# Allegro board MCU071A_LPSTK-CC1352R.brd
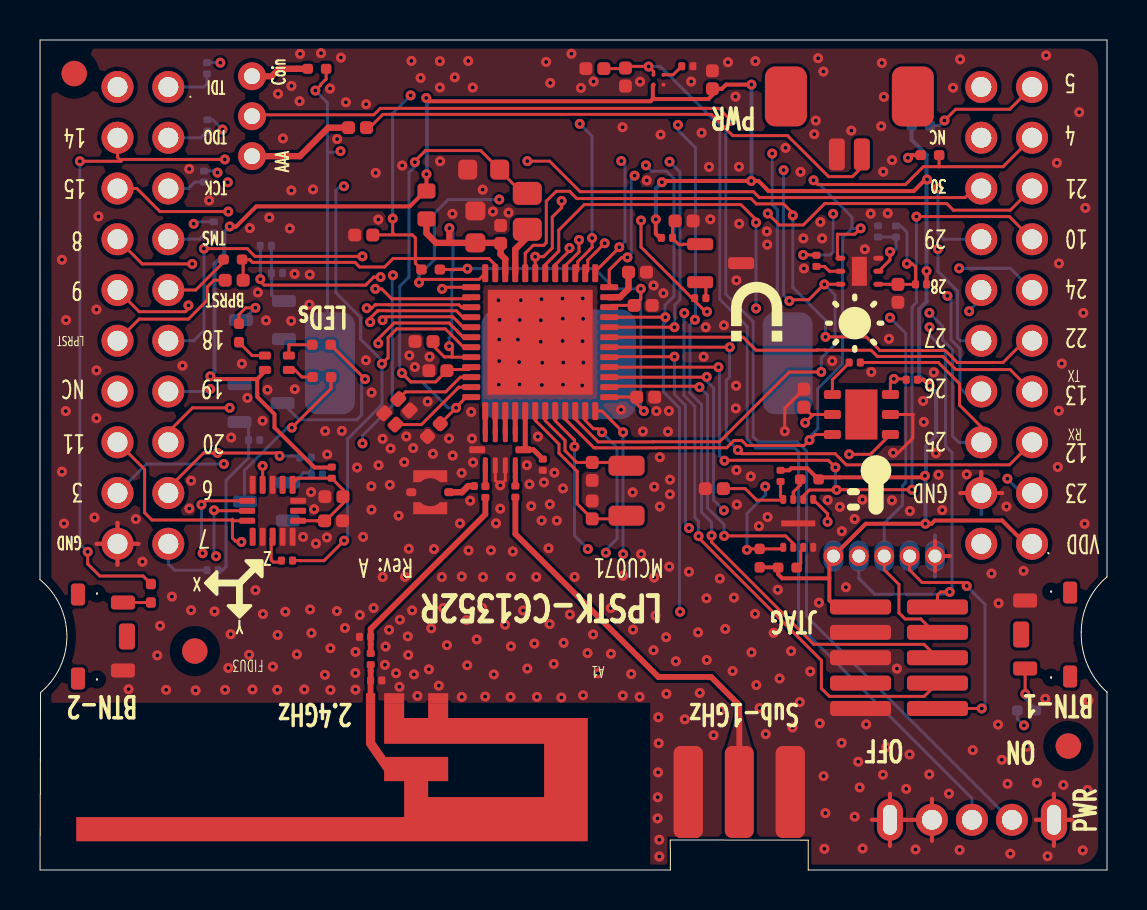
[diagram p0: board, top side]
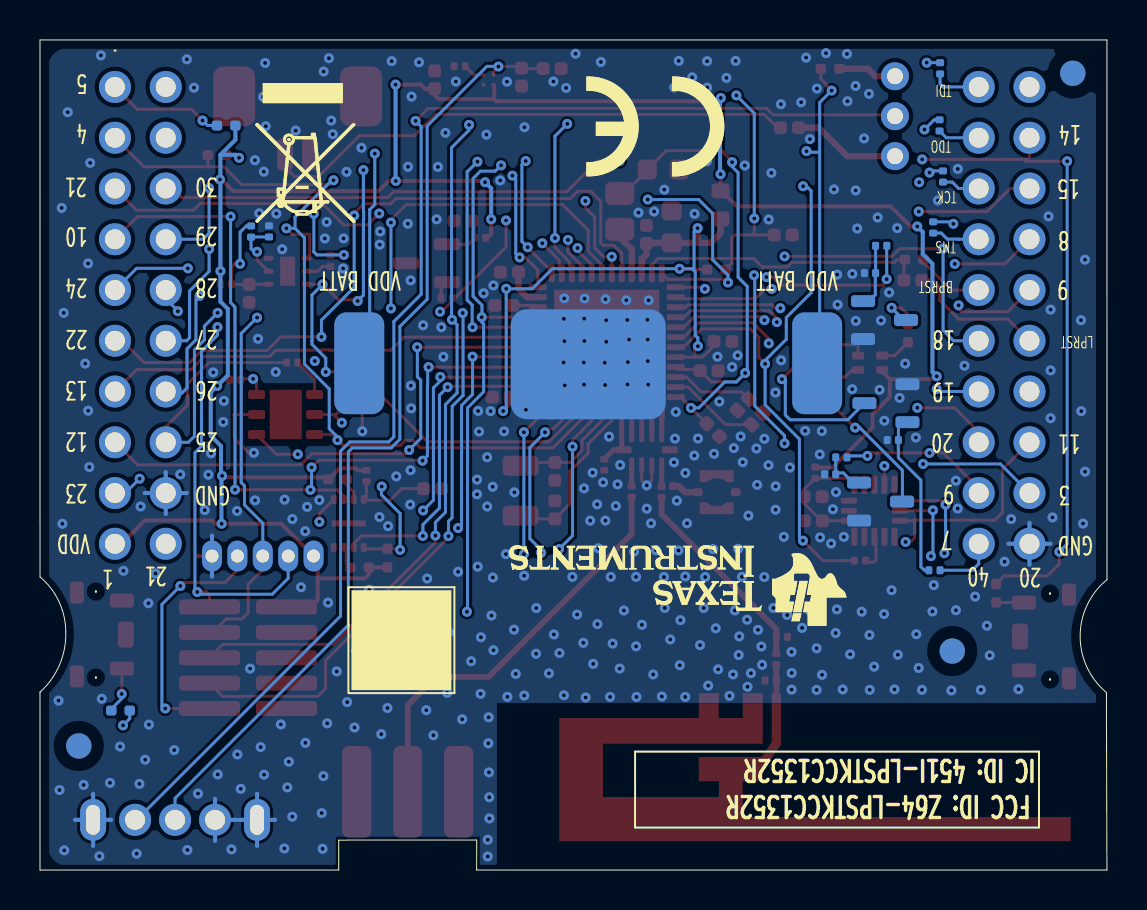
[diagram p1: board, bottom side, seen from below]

Outline 53.37 x 41.54 mm; copper layers: TOP, L2, L3, BOTTOM. Coordinates in mm from the lower left corner of the outline.
Outline path: 0,14.53 arc(1.35,11.71) 0.03,8.88 arc(0.03,8.84) 0.03,8.81 0,0 31.53,0 31.52,1.5 38.43,1.5 38.42,0 53.37,0 53.37,8.91 53.36,8.9 arc(52.39,10.27) 52.08,11.91 arc(52.42,13.43) 53.36,14.67 53.37,41.54 0,41.54 0,14.53

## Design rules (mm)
constraint set DEFAULT: min track width 0.15

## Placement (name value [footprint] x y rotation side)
A1  2.4GHz  [ANTENNA_DN007N]  16.53 8.6 180 top
BT1  BAT-HLD-001  [BAT_BATHLD001N]  37.4 25.36 180 bottom
C1  22uF  [CAPC1608X100A2N]  22.99 35.05 180 top
C2  100nF  [CAPC1005X60A2N]  20.35 24.99 180 top
C3  100nF  [CAPC1005X60A2N]  20.02 22.34 225 top
C4  100nF  [CAPC1005X60A2N]  29.84 23.67 0 top
C5  100nF  [CAPC1005X60A2N]  29.72 28.26 0 top
C6  100nF  [CAPC1005X60A2N]  19.66 26.45 180 top
C7  22uF  [CAPC1608X100A2N]  21.77 31.39 90 top
C8  100nF  [CAPC1005X60A2N]  23.04 31.36 90 top
C9  DNI  [CAPC0603X35B2N]  21.72 19.21 0 top
C10  100nF  [CAPC1005X60A2N]  16.64 31.78 180 top
C11  12pF  [CAPC0603X35B2N]  22.27 19.21 270 top
C12  1.2pF  [CAPC0603X35B2N]  16.54 10.84 270 top
C13  DNI  [CAPC0603X35B2N]  16.54 11.67 180 top
C14  DNI  [CAPC0603X35B2N]  16.54 9.49 0 top
C15  12pF  [CAPC1005X60A2N]  27.62 17.57 90 top
C16  12pF  [CAPC1005X60A2N]  27.62 20.4 270 top
C17  1uF  [CAPC1005X60A2N]  29.43 29.92 0 top
C18  100nF  [CAPC0603X35B2N]  25.15 20.56 270 top
C19  100nF  [CAPC0603X35B2N]  23.78 19.22 270 top
C20  100nF  [CAPC1005X60A2N]  34.18 19.09 180 top
C21  100nF  [CAPC1005X60A2N]  38.2 23.16 90 top
C22  100nF  [CAPC1005X60A2N]  31.76 32.48 0 top
C23  100nF  [CAPC1005X60A2N]  14.23 17.47 0 top
C24  100nF  [CAPC1005X60A2N]  15.15 18.68 180 top
C25  100nF  [CAPC1005X60A2N]  42.91 29.31 270 top
C26  100nF  [CAPC1005X60A2N]  29.28 40.13 270 top
C27  100nF  [CAPC1005X60A2N]  33.63 39.1 90 top
C28  1uF  [CAPC1005X60A2N]  28.2 40.11 180 top
CR1  RF-W5HR15HS-A53  [LED_RFW5HR15HSA53_A2N]  12.45 25.03 90 top
FIDU1  FIDU_1.27mm  [FID127X142]  1.71 39.86 0 top
FIDU2  FIDU_1.27mm  [FID127X142]  51.43 6.2 0 top
FIDU3  FIDU_1.27mm  [FID127X142]  7.74 10.96 180 top
FIDU4  FIDU_1.27mm  [FID127X142]  51.43 6.21 180 bottom
FIDU5  FIDU_1.27mm  [FID127X142]  7.74 10.96 180 bottom
FIDU6  FIDU_1.27mm  [FID127X142]  1.71 39.87 180 bottom
FL1  BLM18HE152SN1  [FIL_BLM18HE152SN1DN]  19.33 32.58 90 top
J1  SLE-100010011  [DONGGUAN_SLE100010011_A2N]  34.97 3.91 180 top
J2  313220S1411  [HARWIN_M209761046B]  49.62 16.33 90 top
J3  313220S1411  [HARWIN_M209761046B]  6.42 16.33 90 top
L1  6.8uH  [INDC2012X150A2N]  24.37 32.06 90 top
LOGO1  Logo_HALL_EFFECT_SENSOR  [LABEL_HALL_EFFECT_SENSOR_TI]  33.72 26.61 180 top
LOGO2  Logo_THERMOSTAT  [LABEL_THERMOSTAT_TI]  41.37 19.63 180 top
LOGO3  Logo_ACCELEROMETER  [LABEL_ACCELEROMETER_TI]  9.74 14.03 0 top
LOGO4  Logo_LIGHT_SENSOR  [LABEL_LIGHT_SENSOR_TI]  41.1 27.4 0 top
LOGO5  TI_LOGO  [TI_LOGO_1]  14.03 12.23 0 bottom
LOGO6  CE_Logo  [CE_MARKING]  21.76 39.71 0 bottom
LOGO7  FCC ID: Z64-LPSTK1352R  [LABEL_FOR_EVALUATION_ONLY]  23.54 2.39 180 bottom
LOGO8  TRASH_7mm  [TRASH_7MM]  38.23 39.38 0 bottom
LOGO9  ESD_Logo_5x5mm  [ESD_LABEL_5X5]  32.79 14 0 bottom
LOGO10  IC ID: 451I-LPSTKCC1352R  [LABEL_FOR_EVALUATION_ONLY]  23.45 2.28 180 bottom
M1  MJ-6B2.0X4.5  [SAMTEC_SNT100BKG]  11.78 34.28 90 top
NOREF  -  []  38.42 0 0 top
NOREF#2  -  []  0 0 0 top
NOREF#3  -  []  53.37 0 90 top
NOREF#4  -  []  53.37 0 90 top
NOREF#5  -  []  39.37 -0.48 180 top
NOREF#6  -  []  31.53 0 90 top
NOREF#7  -  []  -181.43 -169.73 0 top
NOREF#8  -  []  -17.44 -44.66 0 top
NOREF#9  -  []  53.36 14.67 90 top
NOREF#10  -  []  0 41.54 0 top
NOREF#11  -  []  1.35 11.76 0 top
P1  MM5829-2700  [MURATA_MM58292700RJ4_A2N]  20.47 18.91 180 top
P2  FTSH-105-01-F-DV-K  [SAMTEC_FTSH10501FDVK_A2N]  41.04 13.16 270 top
P3  M52-040023V0545  [HARWIN_M52040023V0545_A2B]  39.68 15.71 0 top
P4  CNT-1147H-02  [CNT_CNT1147H02_A2N]  41.11 35.81 180 top
P5  3220103S1210880  [HARWIN_M222010305_A2B]  10.61 35.73 90 top
PCB1  As Per Fab Drawing-MCU071  [TI_MCUXX]  17.49 39.36 180 bottom
Q1  MMBT2222AL  [SOT95P237X111-3A2N]  12.2 28.47 270 bottom
Q2  MMBT2222AL  [SOT95P237X111-3A2N]  9.98 22.41 90 bottom
Q3  MMBT2222AL  [SOT95P237X111-3A2N]  12.4 19.39 270 bottom
R1  100k  [RESC1005X40B2N]  19.08 30.05 0 top
R2  DNI  [RESC0603X35B2N]  8.69 31.88 90 bottom
R3  DNI  [RESC0603X35B2N]  8.2 34.43 90 bottom
R4  0  [RESC0603X35B2N]  8.38 36.98 90 bottom
R5  0  [RESC0603X35B2N]  8.35 39.84 90 bottom
R6  DNI  [RESC1005X40B2N]  10.11 30.55 180 top
R7  0  [RESC1005X40A2N]  10.16 29.52 180 top
R8  220  [RESC1005X40B2N]  9.95 27.34 270 top
R9  180  [RESC1005X40B2N]  14.56 24.67 180 top
R10  180  [RESC1005X40B2N]  14.54 26.29 180 top
R11  4.7k  [RESC0603X35B2N]  11.57 31.24 180 bottom
R12  100k  [RESC0603X35B2N]  12.13 29.87 180 bottom
R13  4.7k  [RESC0603X35B2N]  8.91 15 180 bottom
R14  100k  [RESC0603X35B2N]  10.99 21.52 180 bottom
R15  3.3k  [RESC1005X40B2N]  44.97 35.78 180 top
R16  3.3k  [RESC1005X40B2N]  44.52 37.26 180 bottom
R17  100  [RESC1005X40B2N]  49.8 7.98 180 bottom
R18  100  [RESC1005X40B2N]  5.55 13.39 90 top
R19  4.7k  [RESC0603X35B2N]  13.57 20.65 180 bottom
R20  100k  [RESC0603X35B2N]  14.13 19.81 180 bottom
R21  2.2k  [RESC1005X40B2N]  35.99 16.07 270 top
R22  DNI  [RESC1005X40B2N]  38.02 19.55 0 top
R23  DNI  [RESC1005X40B2N]  37.84 15.14 180 top
R24  0  [RESC0603X35B2N]  37.04 20 270 top
R25  0  [RESC0603X35B2N]  43.33 24.54 0 top
R26  0  [RESC0603X35B2N]  31.64 31.64 180 top
R27  0  [RESC0603X35B2N]  41.03 25.4 180 top
R28  0  [RESC0603X35B2N]  32.74 28.62 0 top
R29  0  [RESC0603X35B2N]  43.79 29.31 0 top
R30  0  [RESC0603X35B2N]  14.59 19.61 90 top
R31  0  [RESC0603X35B2N]  12.63 15.49 180 top
R32  0  [RESC0603X35B2N]  38.84 30.77 270 top
R33  0  [RESC1005X40A2N]  15.43 37.15 0 top
R34  DNI  [RESC1005X40B2N]  13.39 40.1 0 top
R35  100k  [RESC0603X35B2N]  32.66 40.23 180 top
R36  DNI  [RESC0603X35B2N]  42.81 31.67 90 bottom
R37  0  [RESC0603X35B2N]  41.91 31.68 90 bottom
SW1  MTA2-WNC  [SW_MTA2CN]  49.27 13.49 270 top
SW2  MTA2-WNC  [SW_MTA2CN]  4.15 9.99 90 top
SW3  SH-12D01-VGX-H  [SW_SK12D01AVG_A2B]  44.61 2.51 0 top
TR1  0900PC15A0036  [XFMR_IPC1352_A2N]  22.27 20.25 0 top
U1  CC1352R1F3RGZ  [QFNFC50P700X700X100-49A2N]  22.27 22.97 0 top
U2  MX25R8035FZUIL0  [SON50P300X200X60-9B2N]  37.17 16.15 0 top
U3  HDC2080DMB  [SON100P300X300X80-7B2N]  42.53 21.8 90 top
U4  DRV5055A4QDBZ  [SOT95P237X112-3A2N]  33.02 31.32 270 top
U5  ADXL362BCCZ  [LGAFC16S50P300X325X114]  12.63 19.28 180 top
U6  OPT3001  [SON65P200X200X65-7N]  41.93 29.32 90 top
U7  TPS22910AYZV  [BGAFC4C50P89X89X50]  30.68 39.3 0 top
Y1  32.768kHz  [XTAL_FC135_A2N]  29.33 17.73 90 top
Y2  48MHz  [XTAL_XRCMD_A2N]  17.78 22.29 45 top

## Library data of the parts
A1 = ANTENNA_DN007_0
BT1 = BATT_3PINS: User Part Number: #PN; alternate symbols: (BAT_BATHLD001L,BAT_BATHLD001M,BAT_BATHLD001AL,BAT_BATHLD001AM)
C1 C7 = CAPACITOR_2: User Part Number: #PN; alternate symbols: (CAPC1608X100A2L,CAPC1608X100A2M)
C2-C6 C8 C10 C15-C17 C20-C28 = CAPACITOR: User Part Number: #PN; alternate symbols: (CAPC1005X60A2L,CAPC1005X60A2M)
C9 C11-C14 C18 C19 = CAPACITOR: User Part Number: #PN; alternate symbols: (CAPC0603X35B2L,CAPC0603X35B2M)
CR1 = LED_RGB_V1_0: User Part Number: #PN; alternate symbols: (LED_RFW5HR15HSA53_A2L,LED_RFW5HR15HSA53_A2M)
FIDU1-FIDU6 = FIDMARK
FL1 = FILTER_2PIN: alternate symbols: (FIL_BLM18HE152SN1DL,FIL_BLM18HE152SN1DM)
J1 = CONN_COAX_1_J_4MH: User Part Number: #PN
J2 J3 = CONN_HEADER_2X10_P: alternate symbols: (HARWIN_M209761046C,HARWIN_M209761046A)
L1 = INDUCTOR: User Part Number: #PN; alternate symbols: (INDC2012X150A2L,INDC2012X150A2M)
LOGO1 = LABEL_HALL_EFFECT_SENSOR: User Part Number: #PN
LOGO2 = LABEL_THERMOSTAT: User Part Number: #PN
LOGO3 = LABEL_ACCELEROMETER: User Part Number: #PN
LOGO4 = LABEL_LIGHT_SENSOR: User Part Number: #PN
LOGO5 = TI_LOGO_V1
LOGO6 = CE_LABEL_V1
LOGO7 = LABEL_FOR_EVALUATOIN_ONLY_0: User Part Number: #PN
LOGO8 = TRASH_V2: User Part Number: #PN
LOGO9 = ESD_LABEL: User Part Number: #PN
LOGO10 = LABEL_FOR_EVALUATOIN_ONLY_1: User Part Number: #PN
M1 = MECH_SHUNT_JUMPER_V1: User Part Number: #PN
P1 = CONN_COAX_1_1_P_2MH_V1: User Part Number: #PN; alternate symbols: (MURATA_MM58292700RJ4_A2L,MURATA_MM58292700RJ4_A2M)
P2 = CONN_HEADER_2X5: User Part Number: #PN; alternate symbols: (SAMTEC_FTSH10501FDVK_A2L,SAMTEC_FTSH10501FDVK_A2M)
P3 = CONN_HEADER_5_P_S: User Part Number: #PN
P4 = CONN_HEADER_2_P_2MH_V1: User Part Number: #PN; alternate symbols: (CNT_CNT1147H02_A2L,CNT_CNT1147H02_A2M)
P5 = CONN_HEADER_3_P_S: User Part Number: #PN; alternate symbols: (HARWIN_M222010305_A2A,HARWIN_M222010305_A2C)
PCB1 = PCB_V2: User Part Number: #PN
Q1-Q3 = NPN_BEC: User Part Number: #PN; alternate symbols: (SOT95P237X111-3A2L,SOT95P237X111-3A2M)
R1 R6 R8-R10 R15-R18 R21-R23 R34 = RESISTOR: User Part Number: #PN
R2-R5 R11-R14 R19 R20 R24-R32 R35-R37 = RESISTOR: User Part Number: #PN; alternate symbols: (RESC0603X35B2L,RESC0603X35B2M)
R7 R33 = RESISTOR: User Part Number: #PN; alternate symbols: (RESC1005X40A2L,RESC1005X40A2M)
SW1 SW2 = SWITCH_1
SW3 = SWITCH_SLIDE_3PIN_2MH: User Part Number: #PN; alternate symbols: (SW_SK12D01AVG_A2A,SW_SK12D01AVG_A2C)
TR1 = XFMR_IPC1352: User Part Number: #PN
U1 = IC_RF_CC1352_QFN48_V1: User Part Number: #PN; alternate symbols: (QFNFC50P700X700X100-49A2L,QFNFC50P700X700X100-49A2M)
U2 = IC_FLASH_MX25R8035F_USON8: User Part Number: #PN; alternate symbols: (SON50P300X200X60-9B2L,SON50P300X200X60-9B2M)
U3 = IC_PERIPH_HDC2080_DFN6: User Part Number: #PN; alternate symbols: (SON100P300X300X80-7B2L,SON100P300X300X80-7B2M)
U4 = IC_PERIPH_DRV5055_SOT23-3: User Part Number: #PN; alternate symbols: (SOT95P237X112-3A2L,SOT95P237X112-3A2M)
U5 = IC_ACC_ADXL362_LGA16: User Part Number: #PN
U6 = IC_PERIPH_OPT3001_SON6: User Part Number: #PN; alternate symbols: (SON65P200X200X65-7L,SON65P200X200X65-7M)
U7 = IC_PM_TPS22910A_DSBGA4: User Part Number: #PN
Y1 = CRYSTAL: User Part Number: #PN; alternate symbols: (XTAL_FC135_A2L,XTAL_FC135_A2M)
Y2 = XTAL_4_V2: User Part Number: #PN; alternate symbols: (XTAL_XRCMD_A2L,XTAL_XRCMD_A2M)

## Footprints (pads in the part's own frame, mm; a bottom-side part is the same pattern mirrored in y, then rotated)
ANTENNA_DN007N
  rect 0.46x0.5 smd: 1(0,0)
  rect 1.001x0.5 smd: 2(-1.18,0) 3(-3.38,0)
BAT_BATHLD001N
  custom 0.625x0.625 smd: 1(0,0) 2(22.9,0)
  rrect 7.75x5.5 smd: 3(11.45,-0.05)
BGAFC4C50P89X89X50
  round 0.2 smd: A1(0,0) A2(0,0.5) B1(0.5,0) B2(0.5,0.5)
CAPC0603X35B2N
  custom 0.087x0.087 smd: 1(0,0) 2(0.56,0)
CAPC1005X60A2N
  custom 0.16x0.16 smd: 1(0,0) 2(0.9,0)
CAPC1608X100A2N
  custom 0.237x0.237 smd: 1(0,0) 2(1.6,0)
CNT_CNT1147H02_A2N
  custom 0.2x0.2 smd: 1(0,0) 2(1.25,0)
  custom 0.525x0.525 smd: M1(-2.55,-2.9) M2(3.8,-2.9)
DONGGUAN_SLE100010011_A2N
  custom 0.362x0.362 smd: 1(0,0) 2(-2.55,0) 3(2.55,0) 4(2.55,0) 5(-2.55,0)
FID127X142
  round 1.27 smd: 1(0,0)
FIL_BLM18HE152SN1DN
  custom 0.188x0.188 smd: 1(0,0) 2(1.4,0)
HARWIN_M52040023V0545_A2B
  round 1 hole 0.65: 1(0,0) 2(1.27,0) 3(2.54,0) 4(3.81,0) 5(5.08,0)
HARWIN_M209761046B
  round 1.6 hole 1: 1(0,0) 2(0,2.54) 3(2.54,0) 4(2.54,2.54) 5(5.08,0) 6(5.08,2.54) 7(7.62,0) 8(7.62,2.54) 9(10.16,0) 10(10.16,2.54) 11(12.7,0) 12(12.7,2.54) 13(15.24,0) 14(15.24,2.54) 15(17.78,0) 16(17.78,2.54) 17(20.32,0) 18(20.32,2.54) 19(22.86,0) 20(22.86,2.54)
HARWIN_M222010305_A2B
  round 1.4 hole 0.8: 1(0,0) 2(2,0) 3(4,0)
INDC2012X150A2N
  custom 0.287x0.287 smd: 1(0,0) 2(1.8,0)
LED_RFW5HR15HSA53_A2N
  custom 0.1x0.1 smd: 1(0,0) 2(0.72,0) 3(0.72,1.2) 4(0,1.2)
LGAFC16S50P300X325X114
  custom 0.075x0.075 smd: 1(0,0) 2(0.5,0) 3(1,0) 4(1.5,0) 5(2,0) 6(2.275,0.8) 7(2.275,1.3) 8(2.275,1.8) 9(2,2.6) 10(1.5,2.6) 11(1,2.6) 12(0.5,2.6) 13(0,2.6) 14(-0.275,1.8) 15(-0.275,1.3) 16(-0.275,0.8)
MURATA_MM58292700RJ4_A2N
  custom 0.1x0.1 smd: 1(0,0) 2(1.9,0)
  custom 0.15x0.15 smd: M1(0.95,-0.8) M2(0.95,0.8)
QFNFC50P700X700X100-49A2N
  custom 0.075x0.075 smd: 1(0,0) 2(0.5,0) 3(1,0) 4(1.5,0) 5(2,0) 6(2.5,0) 7(3,0) 8(3.5,0) 9(4,0) 10(4.5,0) 11(5,0) 12(5.5,0) 13(6.2,0.7) 14(6.2,1.2) 15(6.2,1.7) 16(6.2,2.2) 17(6.2,2.7) 18(6.2,3.2) 19(6.2,3.7) 20(6.2,4.2) 21(6.2,4.7) 22(6.2,5.2) 23(6.2,5.7) 24(6.2,6.2) 25(5.5,6.9) 26(5,6.9) 27(4.5,6.9) 28(4,6.9) 29(3.5,6.9) 30(3,6.9) 31(2.5,6.9) 32(2,6.9) 33(1.5,6.9) 34(1,6.9) 35(0.5,6.9) 36(0,6.9) 37(-0.7,6.2) 38(-0.7,5.7) 39(-0.7,5.2) 40(-0.7,4.7) 41(-0.7,4.2) 42(-0.7,3.7) 43(-0.7,3.2) 44(-0.7,2.7) 45(-0.7,2.2) 46(-0.7,1.7) 47(-0.7,1.2) 48(-0.7,0.7)
  rect 5.25x5.25 smd: 49(2.75,3.45)
RESC0603X35B2N
  custom 0.087x0.087 smd: 1(0,0) 2(0.56,0)
RESC1005X40A2N
  custom 0.16x0.16 smd: 1(0,0) 2(0.9,0)
RESC1005X40B2N
  custom 0.125x0.125 smd: 1(0,0) 2(0.924,0)
SAMTEC_FTSH10501FDVK_A2N
  custom 0.188x0.188 smd: 1(0,0) 2(0,3.85) 3(1.27,0) 4(1.27,3.85) 5(2.54,0) 6(2.54,3.85) 7(3.81,0) 8(3.81,3.85) 9(5.08,0) 10(5.08,3.85)
SON50P300X200X60-9B2N
  custom 0.075x0.075 smd: 1(0,0) 2(0.5,0) 3(1,0) 4(1.5,0) 5(1.5,2.4) 6(1,2.4) 7(0.5,2.4) 8(0,2.4)
  rect 1.7x0.3 smd: 9(0.75,1.2)
SON65P200X200X65-7N
  oval 0.25x0.5 smd: 1(0,0) 2(0.65,0) 3(1.3,0) 4(1.3,1.9) 5(0.65,1.9) 6(0,1.9)
  rect 1.45x0.75 smd: 7(0.65,0.95)
SON100P300X300X80-7B2N
  rrect 0.45x0.85 smd: 1(0,0) 2(1,0) 3(2,0) 4(2,2.9) 5(1,2.9) 6(0,2.9)
  rect 2.5x1.6 smd: 7(1,1.45)
SOT95P237X111-3A2N
  custom 0.15x0.15 smd: 1(0,0) 2(1.9,0) 3(0.95,2.15)
SOT95P237X112-3A2N
  custom 0.15x0.15 smd: 1(0,0) 2(1.9,0) 3(0.95,2.05)
SW_MTA2CN
  round 0.1 hole 0.9 unplated: (-0.45,1.3) (3.85,1.3)
  custom 0.175x0.175 smd: (-0.4,2.25) (3.8,2.25) 1(0,0) 2(3.4,0)
  custom 0.2x0.2 smd: (1.7,-0.2)
SW_SK12D01AVG_A2B
  round 1.6 hole 1: 1(0,0) 2(2,0) 3(4,0)
  oval 1.3x2.1 hole 0.7x1.5: M1(-2.1,0) M2(6.1,0)
XFMR_IPC1352_A2N
  custom 0.062x0.062 smd: 1(0,0) 2(0.5,0) 3(1,0) 4(1.5,0) 6(1.5,1.56) 7(1,1.56) 8(0.5,1.56) 9(0,1.56)
  custom 0.087x0.087 smd: 5(1.905,0.78) 10(-0.405,0.78)
XTAL_FC135_A2N
  custom 0.25x0.25 smd: 1(0,0) 2(2.5,0)
XTAL_XRCMD_A2N
  custom 0.15x0.15 smd: 1(0,0) 2(1,0) 3(1,0.8) 4(0,0.8)

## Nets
GND: A1.2 A1.3(GND_3) BT1.3(-) C1.2 C2.2 C3.2 C4.2 C5.2 C6.2 C7.2 C8.2 C10.2 C13.2 C14.2 C15.2 C16.2 C17.2 C18.2 C20.2 C21.2 C22.2 C23.2 C24.2 C25.2 C26.2 C27.2 C28.2 J1.2 J1.3 J1.4 J1.5 J2.4 J3.2 P1.2 P1.M1 P1.M2 P2.3 P2.5 P2.9 P3.5 P4.2 Q1.2(EMITTER) Q2.2(EMITTER) Q3.2(EMITTER) R12.1 R14.1 R20.1 R35.1 R37.2 SW1.1 SW2.1 SW3.1 SW3.M1 SW3.M2 TR1.2 TR1.3 TR1.10 U1.49 U2.4 U2.9 U3.2 U4.3 U5.3 U5.5 U5.10 U5.12 U5.13 U5.16 U6.3 U6.7 U7.B1 Y2.2(NC_2) Y2.4
VDD: C27.1 CR1.4(4+) FL1.2 J2.1 P2.1 P3.1 R15.2 R16.2 R21.2 R22.2 R23.2 R24.1 R25.2 R26.2 R29.2 R30.2 U7.A1(VOUT)
VDDR: C1.1 C2.1 C3.1 L1.2 U1.45 U1.48
VDDS: C4.1 C5.1 C6.1 C7.1 C8.1 FL1.1 R1.2 U1.13 U1.22 U1.34 U1.44
ACC_INT: J2.16 R31.1 U1.43
ACC_NCS: J3.6 U1.17 U5.8
BP_RESET: J3.11 R6.2
DCDC_SW: L1.1 U1.33
DIO3: J3.4 U1.8
DIO6_RLED: J3.3 R19.2 U1.11
DIO7_GLED: J3.1 R13.2 U1.12
DIO12_RXD: J2.5 U1.18
DIO13_TXD: J2.7 U1.19
DIO14_BTN2: J3.18 R18.2 U1.20
DIO15_BTN1: J3.16 R17.2 U1.21
DIO16_TDO: P2.6 R4.2 U1.26
DIO17_TDI: P2.8 R5.2 U1.27
DIO19_CTS: J3.7 U1.29
DIO20_FLASH_CS: J3.5 R21.1 U1.30 U2.1
DIO21_BLED: J2.15 R11.2 U1.31
DIO22: J2.9 U1.32
DIO24_ANALOG: J2.11 U1.37
DIO26_ANALOG: J2.8 U1.39
DIO28_ANALOG: J2.12 U1.41
DIO29_ANALOG: J2.14 U1.42
HDC_INT: J2.6 R27.1 U1.38
LP_RESET: J3.10 R7.2
OPT_INT: J2.10 R32.1 U1.40
RX_TX: C18.1 TR1.5 U1.5
WMCU_MISO: J3.14 U1.14 U2.2 U5.7
WMCU_MOSI: J3.12 U1.15(DIO_9) U2.5 U5.6
WMCU_REED: J2.3 R28.1 U1.36
WMCU_RESET: C10.1 P2.10 P3.4 R1.1 R6.1 R7.1 U1.35
WMCU_SCL: J2.17 R15.1 U1.9 U3.6 U6.4
WMCU_SCLK: J2.13 U1.16 U2.6 U5.4
WMCU_SDA: J2.19 R16.1 U1.10 U3.1 U6.6
WMCU_SWO: J3.9 U1.28
WMCU_TCK: P2.4 P3.3 R3.2 U1.25
WMCU_TMS: P2.2 P3.2 R2.2 U1.24
N1017630: C20.1 R24.2 U2.8(VCC)
N1176544: J3.13 R2.1
N1176548: J3.15 R3.1
N1176568: J3.17 R4.1
N1177007: J3.19 R5.1
N1409884: R23.1 U2.3
N1409917: R22.1 U2.7
N2699398: C21.1 R25.1 U3.3 U3.5(VDD)
N2700735: C22.1 R26.1 U4.1(VCC)
N2701534: R36.1 R37.1 U6.2
N2701865: C25.1 R29.1 R36.2 U6.1(VDD)
N2717734: R31.2 U5.11
N2718017: R32.2 U6.5
N2720505: R27.2 U3.4
N2766833: Q1.1 R11.1 R12.2
N2766949: Q2.3 R10.1
N2766991: Q2.1 R13.1 R14.2
N2767546: Q3.3 R9.1
N2767588: Q3.1 R19.1 R20.2
N2769696: Q1.3 R8.1
N2792373: R17.1 SW1.2
N2796131: R18.1 SW2.2
N2848828: R35.2 U7.B2
N2848936: P5.3 R34.1
N3032269: C11.2 C12.1 C13.1
N3032277: A1.1 C12.2 C14.1
N3032725: TR1.9 U1.1
N3032753: TR1.8 U1.2
N3032777: TR1.7 U1.3
N3032785: C15.1 U1.6 Y1.1
N3032797: TR1.6 U1.4
N3032823: C16.1 U1.7 Y1.2
N3032853: C17.1 U1.23
N3032861: U1.46 Y2.3
N3032929: U1.47 Y2.1
N3033151: C19.2 J1.1
N3041603: CR1.2 R10.2
N3041676: CR1.1 R9.2
N3041751: CR1.3 R8.2
N3043961: R28.2 U4.2
N3060472: C9.2 C11.1 TR1.1
N3061599: C9.1 P1.1
N3065409: BT1.1 BT1.2 R34.2
N3065598: P5.2 SW3.3
N3066069: P4.1 R33.2
N3066097: P5.1 R33.1
N3066149: C26.1 C28.1 SW3.2 U7.A2
N3085116: C19.1 TR1.4(UBP_SUB-1_GHZ)
N3297320: C23.1 C24.1 R30.1 U5.1 U5.14(VS)

Pads without a net: FIDU1 1; FIDU2 1; FIDU3 1; FIDU4 1; FIDU5 1; FIDU6 1; J2 2 18 20; J3 8 20; P2 7; P4 M1 M2; U3 7; U5 2 9 15

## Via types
v1: diameter 0.5, hole 0.2, TOP to BOTTOM, 525 vias
v2: diameter 0.5, hole 0.201, TOP to BOTTOM, 25 vias

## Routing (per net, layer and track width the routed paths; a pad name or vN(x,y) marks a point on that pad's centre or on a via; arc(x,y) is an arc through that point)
GND: length 97.7
  TOP w0.15: U3.2 43.67,22.8 43.65,22.78 43.65,21.61 42.9,20.86 42.69,20.86 v1(42.67,20.88) ; TR1.3 23.27,19.5 v1(23.02,19.25) 22.77,19.5 TR1.2 ; v1(37.25,21.96) 37.25,23.11 38.2,24.06
  TOP w0.203: 44.76,15.71 45.52,15.71 ; 44.76,15.71 44.76,16.47 ; 44.76,15.71 44.76,14.96 ; 46.02,18.87 J2.4 ; J2.4 47.08,19.92 ; J2.4 48.13,18.87 ; SW3.M2 50.71,3.82 ; SW3.M2 51.61,2.51 ; SW3.M2 50.71,1.21 ; SW3.M2 49.81,2.51 ; 43.56,2.51 SW3.1 ; SW3.1 44.61,3.57 ; SW3.1 44.61,1.46 ; 2.83,16.33 J3.2 ; J3.2 3.88,17.38 ; J3.2 3.88,15.28 ; J3.2 4.93,16.33 ; SW3.M1 42.51,3.82 ; SW3.M1 41.61,2.51 ; SW3.M1 42.51,1.21 ; SW3.M1 43.41,2.51
  L2 w0.203: 44.76,15.71 44.76,16.47 ; 44.76,15.71 45.52,15.71 ; 44.76,15.71 44.76,14.96 ; J3.2 3.88,17.38 ; J3.2 2.83,16.33 ; J3.2 3.88,15.28 ; J3.2 4.93,16.33 ; SW3.1 44.61,3.57 ; SW3.1 44.61,1.46 ; SW3.1 43.56,2.51 ; SW3.M2 51.61,2.51 ; SW3.M2 50.71,3.82 ; SW3.M2 49.81,2.51 ; SW3.M2 50.71,1.21 ; J2.4 47.08,19.92 ; J2.4 46.02,18.87 ; J2.4 47.08,17.82 ; J2.4 48.13,18.87 ; SW3.M1 43.41,2.51 ; SW3.M1 42.51,3.82 ; SW3.M1 42.51,1.21 ; SW3.M1 41.61,2.51
  L3 w0.203: 49.81,2.51 SW3.M2 ; SW3.M2 50.71,1.21 ; SW3.M2 50.71,3.82 ; SW3.M2 51.61,2.51 ; 41.61,2.51 SW3.M1 ; SW3.M1 42.51,3.82 ; SW3.M1 43.41,2.51 ; SW3.M1 42.51,1.21 ; J3.2 4.93,16.33 ; J3.2 2.83,16.33 ; J3.2 3.88,17.38 ; J3.2 3.88,15.28 ; J2.4 48.13,18.87 ; J2.4 46.02,18.87 ; J2.4 47.08,17.82 ; J2.4 47.08,19.92 ; SW3.1 44.61,3.57 ; SW3.1 43.56,2.51 ; SW3.1 44.61,1.46 ; 44.76,15.71 45.52,15.71 ; 44.76,15.71 44.76,14.96 ; 44.76,15.71 44.76,16.47
  BOTTOM w0.203: 41.61,2.51 SW3.M1 ; SW3.M1 42.51,1.21 ; SW3.M1 42.51,3.82 ; SW3.M1 43.41,2.51 ; 43.56,2.51 SW3.1 ; SW3.1 44.61,1.46 ; SW3.1 44.61,3.57 ; J2.4 48.13,18.87 ; J2.4 47.08,19.92 ; J2.4 47.08,17.82 ; J2.4 46.02,18.87 ; 3.88,15.28 J3.2 ; J3.2 4.93,16.33 ; J3.2 3.88,17.38 ; J3.2 2.83,16.33 ; SW3.M2 50.71,3.82 ; SW3.M2 51.61,2.51 ; SW3.M2 50.71,1.21 ; SW3.M2 49.81,2.51 ; 44.76,14.69 44.76,16.74
  vias: v1(1.1,30.54) v1(1.1,19.94) v1(1.29,22.97) v1(1.2,17.34) v1(1.3,27.52) v1(2.73,17.65) v1(2.82,28.05) v1(2.82,25.01) v1(2.82,22.61) v1(2.92,32.71) v1(4.43,9.05) v1(4.79,17.56) v1(5.12,15.43) v1(5.87,10.74) v1(6.01,12.23) v1(6.31,9.02) v1(6.6,13.68) v1(7.13,25.24) v1(7.46,35.09) v1(7.47,18.09) v1(7.56,19.49) v1(7.55,13) v1(7.78,8.99) v1(8.46,33.51) v1(8.66,14.26) v1(8.73,12.94) v1(9.26,9.02) v1(9.42,10.11) v1(9.56,21.65) v1(9.54,11.8) v1(10.1,25.34) v1(10.37,23.63) v1(10.49,32.12) v1(10.46,10.77) v1(10.63,9.04) v1(10.78,14) v1(10.9,28.9) v1(11.14,22.48) v1(11.15,12.81) v1(11.3,27.5) v1(11.38,24.03) v1(11.47,32.66) v1(11.65,10.18) v1(11.88,11.76) v1(11.87,9.02) v1(11.9,38.84) v1(12.15,36.61) v1(12.27,12.93) v1(12.49,32.1) v1(12.58,39.24) v1(12.57,34.01) v1(12.56,27.48) v1(12.74,29.83) v1(12.74,24.06) v1(12.85,10.79) v1(12.98,38.48) v1(13.01,40.84) v1(13.16,16.67) v1(13.22,9.04) v1(13.49,29.8) v1(13.47,28.3) v1(13.56,18.91) v1(13.51,13.04) v1(13.57,11.86) v1(13.65,34.06) v1(13.71,18.06) v1(13.8,16.34) v1(14.05,40.88) v1(14.26,21.97) v1(14.25,9.77) v1(14.37,20.8) v1(14.35,16.65) v1(14.51,39.11) v1(14.53,11.1) v1(14.53,9.01) v1(14.86,36.58) v1(14.85,12.96) v1(15.05,40.66) v1(15.1,21.98) v1(15.25,12.12) v1(15.3,38.42) v1(15.78,10.92) v1(15.77,9.86) v1(15.78,9.03) v1(15.86,20.14) v1(16,12.76) v1(16.16,16.67) v1(16.31,38.32) v1(16.3,25.51) v1(16.58,23.89) v1(16.57,19.21) v1(16.58,18.03) v1(16.69,13.11) v1(16.79,34.89) v1(16.92,32.55) v1(16.93,20.26) v1(17.14,21.58) v1(17.14,14.66) v1(17.29,11.19) v1(17.25,10.27) v1(17.5,19.28) v1(17.46,12.02) v1(17.53,21.1) v1(17.81,9.85) v1(17.93,17.73) v1(17.98,9.17) v1(18,12.53) v1(18.12,35.26) v1(18.22,20.41) v1(18.26,14.67) v1(18.32,21.7) v1(18.39,11.69) v1(18.47,25.75) v1(18.45,16.08) v1(18.42,10.76) v1(18.58,40.49) v1(18.67,21.12) v1(18.61,12.99) v1(18.75,25.17) v1(18.7,9.79) v1(18.88,8.71) v1(19.03,39.64) v1(19.39,23.45) v1(19.48,25.69) v1(19.45,10.04) v1(19.57,12.1) v1(19.65,20.83) v1(19.7,16.06) v1(19.95,9.23) v1(20,40.48) v1(20,39.16) v1(20.01,35.47) v1(20.1,14.66) v1(20.17,13.11) v1(20.35,11.25) v1(20.46,21.59) v1(20.63,32.84) v1(20.64,20.74) v1(20.74,39.67) v1(21.09,19.87) v1(21.01,17.35) v1(21.09,14.69) v1(21.09,8.66) v1(21.34,12.51) v1(21.37,10.25) v1(21.42,40.49) v1(21.43,15.99) v1(21.57,22.93) v1(21.52,18.49) v1(21.64,39.16) v1(21.61,21.59) v1(21.66,20.4) v1(21.84,11.54) v1(22.14,34.05) v1(22.16,14.66) v1(22.12,13.11) v1(22.26,8.68) v1(22.55,16) v1(22.65,32.95) v1(22.7,9.79) v1(22.81,17.35) v1(23.02,18.08) v1(23.26,12.27) v1(23.43,32.9) v1(23.55,14.67) v1(23.55,11.2) v1(23.53,8.66) v1(23.65,15.94) v1(24.16,12.99) v1(24.35,20.27) v1(24.37,10.08) v1(24.48,19.3) v1(24.57,18.21) v1(24.73,11.33) v1(24.82,14.67) v1(24.85,8.66) v1(24.9,21.69) v1(25.09,17.49) v1(25.2,19.4) v1(25.31,40.44) v1(25.44,16.1) v1(25.49,12.31) v1(25.52,39.39) v1(25.5,18.3) v1(25.7,10.32) v1(25.73,19.89) v1(25.85,17.49) v1(26.08,8.63) v1(26.16,19.1) v1(26.19,11.37) v1(26.58,40.85) v1(26.5,12.79) v1(26.74,14.67) v1(27.05,39.14) v1(27.16,8.74) v1(27.38,10.86) v1(27.69,39.46) v1(27.66,11.79) v1(27.91,9.84) v1(28.55,13.11) v1(28.56,10.82) v1(29.06,23.04) v1(29.14,37.17) v1(29.15,14.73) v1(29.15,8.73) v1(29.57,9.81) v1(29.64,18.9) v1(29.66,12.03) v1(29.99,8.67) v1(30.01,39.45) v1(30.06,15.81) v1(30.16,21.95) v1(30.35,34.51) v1(30.69,29.26) v1(30.69,11) v1(30.72,19.18) v1(30.72,14.64) v1(30.79,12.73) v1(30.83,22.97) v1(30.9,3.64) v1(30.89,2.58) v1(30.93,7.64) v1(30.94,6.34) v1(30.91,4.89) v1(30.97,1.51) v1(30.97,0.68) v1(31.04,36.8) v1(31,20.66) v1(31,18.19) v1(31.18,28.86) v1(31.31,11.65) v1(31.33,8.82) v1(31.46,22.97) v1(31.41,21.94) v1(31.47,15.18) v1(31.51,19.54) v1(31.51,18.8) v1(31.8,10.45) v1(32.25,7.54) v1(32.46,14.93) v1(32.57,39.46) v1(32.91,11.89) v1(33.09,36.89) v1(33,8.87) v1(33.19,25.69) v1(33.3,27.16) v1(33.33,13.6) v1(33.35,10.51) v1(33.46,35.19) v1(33.53,32.57) v1(33.69,6.75) v1(34,14.59) v1(34.05,8) v1(34.2,27.26) v1(34.27,12.06) v1(34.41,40.42) v1(34.64,9.96) v1(34.78,38.71) v1(34.71,13.63) v1(34.83,29.51) v1(34.82,24.24) v1(34.8,23.11) v1(34.83,20.01) v1(34.85,18.29) v1(34.96,35.19) v1(34.97,32.34) v1(35.55,19.7) v1(35.58,10.89) v1(35.78,40.48) v1(35.76,12.82) v1(35.83,9.26) v1(35.96,17.21) v1(35.99,8.11) v1(36.35,31.96) v1(36.37,31.3) v1(36.39,17.67) v1(36.3,6.8) v1(36.69,11.87) v1(36.9,14.02) v1(36.99,9.58) v1(37.29,36.14) v1(37.57,10.96) v1(37.64,7.13) v1(38.04,34.94) v1(38,8.4) v1(38.18,31.61) v1(38.21,30.1) v1(38.52,9.94) v1(38.72,36.83) v1(38.8,37.5) v1(38.91,40.63) v1(38.96,13.38) v1(39.03,32.43) v1(39,7.34) v1(39.18,39.96) v1(39.12,31.61) v1(39.19,4.7) v1(39.28,2.85) v1(39.23,1.06) v1(39.39,18.51) v1(39.62,25.47) v1(40.01,18.17) v1(40.09,6.36) v1(40.1,16.96) v1(40.31,14.15) v1(40.58,37) v1(40.74,17.57) v1(40.75,2.67) v1(40.92,5.42) v1(41,4.13) v1(41.13,18.54) v1(41.14,1.08) v1(41.25,31.07) v1(41.32,7.29) v1(41.54,32.85) v1(41.58,24.92) v1(42.07,37.22) v1(42.11,40.39) v1(42.17,34.95) v1(42.16,4.77) v1(42.21,38.69) v1(42.33,6.15) v1(42.4,32.87) v1(42.46,26.59) v1(42.62,35.52) v1(42.61,18.5) v1(42.86,10.08) v1(43.33,4.06) v1(43.49,5.78) v1(43.51,17.97) v1(43.79,1.03) v1(44.17,23.48) v1(44.2,22.42) v1(44.48,4.79) v1(44.7,24.9) v1(44.81,20.86) v1(44.94,19.78) v1(45.12,18.01) v1(45.46,3.83) v1(45.66,39.15) v1(45.99,1) v1(46.02,40.57) v1(46.35,19.8) v1(46.65,6) v1(47.59,14.84) v1(47.94,13.35) v1(47.92,7.28) v1(48.11,5.52) v1(48.34,18.19) v1(48.39,4.31) v1(48.53,0.82) v1(49.19,14.97) v1(49.36,6.18) v1(49.87,4.36) v1(50.28,8.57) v1(50.32,40.77) v1(50.4,0.69) v1(50.86,35.39) v1(50.96,30.36) v1(50.96,22.99) v1(50.9,20.17) v1(51.1,25.34) v1(51.18,4.26) v1(51.98,37.92) v1(52.18,27.88) v1(52.15,0.98) v1(52.28,33.14) v1(52.25,17.33) v1(52.39,4) v1(52.44,8.48) v2(22.93,28.51) v2(22.99,27.53) v2(22.97,26.55) v2(22.97,25.47) v2(22.95,24.29) v2(23.99,27.53) v2(23.9,26.55) v2(23.96,25.42) v2(23.98,24.3) v2(24.04,28.52) v2(25.08,28.57) v2(25.05,27.51) v2(25.04,26.44) v2(25.12,25.39) v2(25.1,24.27) v2(26.13,28.6) v2(26.15,27.59) v2(26.14,26.48) v2(26.17,25.4) v2(26.16,24.29) v2(27.15,28.61) v2(27.16,27.59) v2(27.14,26.47) v2(27.18,25.4) v2(27.12,24.25)
VDD: length 122.7
  TOP w0.2: U7.A1 30.65,39.27 30.65,38.58 ; v1(19.33,34.82) FL1.2 19.27,33.98 18.5,33.21 10.82,33.21 9.8,32.19 9.5,32.19 v1(9.49,32.21) ; 10.86,24.57 8.66,24.57 v1(8.52,24.71) ; 10.86,24.57 10.86,23.85 10.87,23.84 10.87,23.67 11.73,22.81 11.73,22.14 13.73,20.14 14.57,20.14 R30.2 ; 10.86,24.57 11.25,24.96 CR1.4 ; 39.48,14.6 37.12,14.6 36.92,14.8 R23.2 36.91,15.15 R21.2 ; 39.48,14.6 39.48,15.51 P3.1 41.3,17.33 v1(44.28,17.33) 44.59,17.33 44.75,17.49 48.12,17.49 49.29,16.33 J2.1 ; 39.48,14.6 39.48,13.5 39.82,13.16 P2.1 ; v1(19.32,38.64) 19.48,38.47 30.54,38.47 30.65,38.58 ; v1(30.8,32.57) 30.8,31.84 31,31.64 R26.2 ; v1(35.58,39.31) 34.32,39.31 34.11,39.1 C27.1 33.63,38.78 33.43,38.58 30.65,38.58 ; v1(44.26,19.73) 44.18,19.65 39.99,19.65 39.99,19.65 39.04,19.65 38.94,19.55 38.93,19.55 38.37,20.11 37.57,20.11 37.47,20 R24.1 ; R25.2 44.2,24.54 v1(44.5,24.23) ; v1(44.34,29.97) 44.34,29.32 44.34,29.31 ; v1(43.41,35.64) 43.48,35.64 43.62,35.78 R15.2 ; v1(31.11,34.42) 31.12,34.42 31.19,34.48 v1(35.57,34.48) 35.93,34.48 36.44,33.98 43.7,33.98 44.28,34.56 v1(44.37,34.56)
  BOTTOM w0.2: v1(43.41,35.64) 43.56,35.79 44.34,35.79 ; 44.34,35.79 43.59,36.54 R16.2 ; 44.34,35.79 44.34,34.58 v1(44.37,34.56) 44.34,34.53 v1(44.34,29.97) 44.34,28.45 43.97,28.08 43.97,24.76 v1(44.5,24.23) 44.83,23.91 44.83,21.73 44.31,21.22 44.31,19.73 ; v1(35.57,34.48) 35.58,34.5 v1(35.58,39.31) ; v1(44.28,17.33) 44.29,17.34 44.29,19.71 44.31,19.73 ; v1(8.52,24.71) 8.73,24.92 8.73,30.34 9.22,30.83 9.22,31.93 v1(9.49,32.21) ; v1(44.26,19.73) 44.31,19.73 ; v1(19.33,34.82) 19.35,34.85 19.35,38.6 v1(19.32,38.64) ; v1(30.8,32.57) 30.8,34.12 v1(31.11,34.42)
VDDR: length 27.2
  TOP w0.15: U1.45 21.45,25.05 20.41,25.05 C2.1 19.79,24.43 18.55,24.43 v1(18.1,24.87) ; C3.1 v1(20.81,23.13) 20.81,23.16 21.32,23.67 U1.48 ; v1(18.75,35.42) 18.75,35.48 19.28,36.01 22.04,36.01 C1.1 22.99,35.01 24.14,33.86 L1.2
  BOTTOM w0.15: v1(20.81,23.13) 20.41,23.13 19.12,24.43 18.53,24.43 18.1,24.86 v1(18.1,24.87) 17.99,24.98 17.99,29.21 18.45,29.67 18.45,34.9 18.75,35.2 v1(18.75,35.42)
VDDS: length 37.9
  TOP w0.15: v1(21.38,30.09) 21.34,30.05 R1.2 ; U1.13 C4.1 29.84,23.33 v1(30.2,22.97) ; v1(30.05,29.09) 30.05,28.58 29.73,28.26 C5.1 28.56,28.26 U1.22 ; 20.62,25.68 20.22,25.68 19.66,26.24 C6.1 ; 20.62,25.68 20.63,25.67 U1.44 ; 20.62,25.68 20.62,26.06 v1(20.46,26.21) ; C8.1 23.01,31.39
  TOP w0.32: U1.34 23.27,30.58 23.04,30.81 C8.1 ; FL1.1 19.33,31.87 19.81,31.39 20.48,31.39 ; 20.48,31.39 C7.1 23.01,31.39 ; 20.48,31.39 v1(20.48,32.12)
  BOTTOM w0.15: v1(20.48,32.12) 20.65,31.95 20.65,30 ; v1(20.47,26.22) 20.47,26.63 20.59,26.76 20.59,29.94 20.65,30 ; 20.65,30 20.74,30.09 v1(21.38,30.09) 27.74,30.09 28.74,29.09 v1(30.05,29.09) 30.05,23.12 v1(30.2,22.97)
ACC_INT: length 62.4
  TOP w0.15: U1.43 21.19,26.17 20.27,27.08 17.84,27.08 17.41,26.65 17.41,25.64 v1(17.1,25.33) ; J2.16 46.73,34.11 46.27,33.65 35.98,33.65 35.68,33.95 27.02,33.95 25.49,35.48 v1(24.38,35.48) ; v1(15.21,16.48) 14.21,15.48 13.02,15.48 13.01,15.49 R31.1
  L3 w0.15: v1(24.38,35.48) 24.13,35.72 21.06,35.72 19.62,34.28 15.26,34.28 v1(15.2,34.22)
  BOTTOM w0.15: v1(15.21,16.48) 15.38,16.66 15.38,21.57 17.1,23.29 v1(17.1,25.33) 17.1,25.5 16.04,26.56 16.04,27.22 16.04,27.23 16.04,27.65 14.8,28.89 14.8,33.99 14.95,34.14 15.06,34.14 15.14,34.22 v1(15.2,34.22)
ACC_NCS: length 47.7
  TOP w0.15: 9.63,17.55 9.63,16.61 9.78,16.46 10.03,16.46 10.07,16.42 v1(10.07,16.42) ; 9.63,17.55 9.7,17.48 10.36,17.48 ; 9.63,17.55 9.59,17.52 5.6,17.52 5.23,17.88 5.23,20.05 J3.6 ; U1.17 28.49,25.69 v1(31.73,25.69)
  L3 w0.15: v1(32.46,17.11) 32.46,17.05 31.48,16.08 31.48,16.07 31.2,15.79 31.2,15.79 29.59,14.19 12.15,14.19 10.07,16.27 v1(10.07,16.42)
  BOTTOM w0.15: v1(32.46,17.11) 32.28,17.29 32.28,23.25 31.73,23.8 v1(31.73,25.69)
BP_RESET: length 3.5
  TOP w0.15: 6.42,29.03 7.79,29.03 9.18,30.42 R6.2
DCDC_SW: length 2.4
  TOP w0.32: L1.1 24.37,31.67 23.77,31.07 U1.33
DIO3: length 35.5
  TOP w0.15: U1.8 25.77,22.48 26.73,21.52 v1(26.73,21.19)
  L3 w0.15: v1(9.2,20.32) 9.2,18.83 12.91,15.12 15.79,15.12 17.25,16.58 26.57,16.58 27.08,16.06 v1(27.4,16.06)
  BOTTOM w0.15: J3.4 5.33,20.32 v1(9.2,20.32) ; v1(27.4,16.06) 26.73,16.73 v1(26.73,21.19)
DIO6_RLED: length 39.6
  TOP w0.15: J3.3 6.42,19.11 8.18,20.87 v1(8.88,20.87) 11.84,20.87 v1(11.98,20.73) ; U1.11 27.27,22.5 27.69,22.08 27.92,22.08 28.1,21.91 v1(28.11,21.91)
  L3 w0.15: v1(8.88,20.87) 8.7,20.7 8.7,18.9 12.79,14.82 15.92,14.82 16.56,15.47 27.69,15.47 28.1,15.88 v1(28.3,15.88)
  BOTTOM w0.15: v1(11.98,20.73) 12.93,20.73 R19.2 ; v1(28.11,21.91) 28.11,21.9 28.87,21.14 28.87,16.58 28.3,16.02 v1(28.3,15.88)
DIO7_GLED: length 35.6
  TOP w0.15: v1(29.16,21.91) 28.11,22.97 U1.12
  L3 w0.15: v1(29.16,15.81) 29,15.81 28.35,15.17 16.69,15.17 16.04,14.52 12.66,14.52 11.97,15.21 11.95,15.21 10.11,17.06 7.15,17.06 J3.1
  BOTTOM w0.15: v1(29.16,21.91) v1(29.16,15.81) ; J3.1 6.42,15.32 6.74,15 8.35,15
DIO12_RXD: length 27
  TOP w0.15: v1(34.9,21.02) 35.09,20.84 39.77,20.84 40.33,20.28 48.49,20.28 J2.5 ; v1(34.5,26.17) U1.18
  BOTTOM w0.15: v1(34.5,26.17) 34.49,26.16 34.49,24.68 34.32,24.51 34.32,21.6 v1(34.9,21.02)
DIO13_TXD: length 22.3
  TOP w0.15: U1.19 35.16,26.67 35.82,26.01 38.87,26.01 38.88,26.03 39.27,26.03 39.29,26.01 41.57,26.01 41.88,25.7 45.15,25.7 45.81,25.05 48.52,25.05 J2.7
DIO14_BTN2: length 68.5
  TOP w0.15: 4.06,35.49 4.04,35.47 v1(1.99,35.47) ; 4.06,35.49 4.14,35.56 v1(9.24,35.56) ; 4.06,35.49 3.88,35.67 3.88,36.65 ; v1(2.39,15.93) 2.39,15.32 2.99,14.72 5.15,14.72 5.55,14.32 R18.2 ; v1(31.73,27.17) U1.20
  L3 w0.15: v1(9.24,35.56) 9.24,35.32 10.05,34.51 11.09,34.51 11.92,35.34 15.19,35.34 16.47,36.62 25.32,36.62 25.68,36.26 29.98,36.26 30.8,35.45 v1(31.49,35.45)
  BOTTOM w0.15: v1(31.49,35.45) 31.99,34.95 32,34.95 32,28.53 31.75,28.27 31.75,27.19 v1(31.73,27.17) ; v1(2.39,15.93) 1.99,16.32 v1(1.99,35.47)
DIO15_BTN1: length 77.7
  TOP w0.15: 3.88,34.11 4.84,34.11 6,32.95 v1(9.42,32.95) ; v1(31.27,27.67) U1.21
  L2 w0.15: v1(9.39,34.42) 9.34,34.36 9.34,33.03 v1(9.42,32.95)
  L3 w0.15: v1(30.31,35.27) 30.31,35.44 29.78,35.96 25.55,35.96 25.19,36.32 16.59,36.32 15.31,35.04 12.05,35.04 11.21,34.21 9.6,34.21 v1(9.39,34.42) ; v1(49.21,7.24) 49.21,7.04 48.83,6.65 40.85,6.65 34.58,12.92 v1(32.01,12.92)
  BOTTOM w0.15: v1(32.01,12.92) 31.98,12.95 31.98,23.13 31.18,23.93 31.18,27.33 31.27,27.42 v1(31.27,27.67) 31.26,27.68 31.26,28.27 31.7,28.71 31.7,34.61 31.34,34.97 30.6,34.97 v1(30.31,35.27) ; v1(49.21,7.24) 48.88,7.57 R17.2
DIO16_TDO: length 70
  TOP w0.15: v1(28.24,31.37) 27.78,30.91 27.39,30.52 27.39,29.99 U1.26 ; v1(33.59,16.74) 33.59,16.41 38.7,11.3 39.41,11.3 39.42,11.29 44.22,11.29 P2.6
  L3 w0.15: v1(28.24,31.37) 28.24,31.12 29.34,30.03 31.42,30.03 31.42,30.03 32.38,30.03 32.76,29.66 v1(32.76,27.54) ; v1(31.91,37.29) 31.91,37.61 31.63,37.88 28.34,37.88 27.32,36.86 25.93,36.86 25.57,37.22 11.5,37.22 10.98,36.71 9.48,36.71 v1(9.13,37.06)
  BOTTOM w0.15: v1(31.91,37.29) 31.91,37.03 32.78,36.15 32.78,27.56 v1(32.76,27.54) 32.51,27.29 32.51,23.88 33.09,23.3 33.09,17.9 33.59,17.4 v1(33.59,16.74) ; v1(9.13,37.06) 8.64,37.54 8.38,37.54
DIO17_TDI: length 63.9
  TOP w0.15: U1.27 26.89,29.99 26.89,30.44 27.48,31.03 27.48,31.03 27.61,31.16 v1(27.61,31.63) ; P2.8 44.22,8.69 39.48,8.69 39.08,9.09 39.08,10.49 32.94,16.63 v1(32.94,16.71)
  L3 w0.15: v1(27.61,31.63) 27.61,31.33 29.21,29.73 31.91,29.73 32.23,29.41 v1(32.23,27.88) ; v1(26.99,37.34) 26.81,37.52 12.2,37.52 11.01,38.71 9.41,38.71 9.02,39.1 v1(9.02,40.4)
  BOTTOM w0.15: v1(32.94,16.71) 32.93,16.72 32.93,17.46 32.75,17.64 32.75,23.21 32.21,23.75 32.21,27.86 v1(32.23,27.88) ; v1(9.02,40.4) 9.02,40.41 8.35,40.41 R5.2 ; v1(27.61,31.63) 27.61,36.72 v1(26.99,37.34)
DIO19_CTS: length 32.1
  TOP w0.15: v1(26.48,31.13) 26.48,31 25.77,30.29 U1.29
  L3 w0.15: v1(8.52,24.07) 9.01,23.58 9.01,22.87 10.68,21.2 13.85,21.2 14.14,21.49 15.98,21.49 v1(16.13,21.35) ; v1(26.48,31.13) 25.88,31.13 24.07,29.32 21.06,29.32 20.4,29.98 17.86,29.98 v1(17.65,29.77)
  BOTTOM w0.15: v1(17.65,29.77) 17.62,29.73 17.62,23.23 16.13,21.74 v1(16.13,21.35) ; 6.42,23.95 8.39,23.95 8.52,24.07 v1(8.52,24.07)
DIO20_FLASH_CS: length 63.6
  TOP w0.15: U1.30 25.27,30.29 25.95,30.96 25.95,32.02 27.23,33.3 35.05,33.3 35.81,32.54 v1(35.81,32.4) ; v1(9.49,23.13) 7.63,23.13 6.42,21.92 J3.5 ; v1(35.36,16.02) 35.41,16.07 R21.1 37.1,16.07 U2.1
  L3 w0.15: v1(9.49,23.13) 11.12,21.5 13.12,21.5 14.07,22.45 21.37,22.45 21.37,22.45 21.76,22.45 21.77,22.45 35.81,22.45 ; v1(35.81,28.11) 35.81,22.45 ; 35.81,22.45 36.27,21.99 v1(36.27,19.19)
  BOTTOM w0.15: v1(36.27,19.19) 36.29,19.17 36.29,18.78 35.36,17.84 v1(35.36,16.02) ; v1(35.81,28.11) v1(35.81,32.4)
DIO21_BLED: length 46.5
  TOP w0.15: v1(17.03,29.67) 16.69,29.67 16.29,29.27 11.21,29.27 11.02,29.47 v1(11.02,29.57) ; v1(36.4,32.85) 36.97,32.28 38.18,32.28 39.25,33.35 45.36,33.35 45.69,33.02 48.53,33.02 J2.15 ; U1.31 v1(24.77,30.69) 25.18,30.69 25.62,31.13 25.62,32.68 26.09,33.14 v1(26.09,33.48)
  L3 w0.15: v1(17.03,29.67) 17.03,30.12 17.18,30.28 20.52,30.28 21.18,29.62 23.69,29.62 v1(24.77,30.69) ; v1(26.09,33.48) 29.03,33.48 29.47,33.04 30.01,33.04 30.01,33.04 36.21,33.04 v1(36.4,32.85)
  BOTTOM w0.15: R11.2 11.02,31.23 v1(11.02,29.57)
DIO22: length 35.5
  TOP w0.15: v1(39.29,26.68) 41.33,26.68 42.01,26 45.28,26 45.88,25.4 48.17,25.4 49.25,26.49 J2.9 ; U1.32 24.27,30.87 24.67,31.26 25.19,31.26 25.32,31.39 25.32,33.47 25.82,33.97 26.48,33.97 26.85,33.6 35.56,33.6 35.83,33.34 37.19,33.34 37.65,32.87 v1(37.65,32.76)
  BOTTOM w0.15: v1(37.65,32.76) 37.65,29.16 39.29,27.52 v1(39.29,26.68)
DIO24_ANALOG: length 54.5
  TOP w0.15: U1.37 20.19,29.17 v1(20.11,29.08)
  L3 w0.15: v1(45.97,30.11) 45.47,30.61 45.47,33.05 44.88,33.64 30.26,33.64 30.26,33.64 29.72,33.64 28.96,34.4 23.72,34.4 23.3,34.82 21.44,34.82 19.99,33.38 16.02,33.38 15.7,33.07 14.52,33.07 14.37,32.92 14.37,27.85 15.37,26.85 17.77,26.85 18.2,27.27 20,27.27 20.05,27.32 20.05,29.02 v1(20.11,29.08)
  BOTTOM w0.15: v1(45.97,30.11) 48.53,30.11 J2.11
DIO26_ANALOG: length 47.8
  TOP w0.15: U1.39 21.08,28.17 20.95,28.29 17.46,28.29 17.46,28.29 16.81,28.29 16.81,28.29 16.76,28.29 16.59,28.12 v1(16.34,28.12)
  L3 w0.15: v1(16.34,28.12) 16.34,28.42 15.01,29.75 15.01,31.11 15.68,31.79 15.7,31.79 15.7,31.79 19.88,31.79 20.05,31.62 23.66,31.62 24.74,32.71 28.96,32.71 29.63,32.03 29.95,32.03 30.45,31.53 34.27,31.53 34.27,31.53 35.27,31.53 35.27,31.53 35.39,31.53 37.28,29.65 37.83,29.65 38.75,28.73 v1(45.39,28.73)
  BOTTOM w0.15: J2.8 47,23.87 46.27,23.87 46.01,24.12 46.01,26.08 45.57,26.53 45.57,28.55 v1(45.39,28.73)
DIO28_ANALOG: length 44
  TOP w0.15: U1.41 21.16,27.17 20.64,27.69 17.3,27.69 v1(17.13,27.52)
  L3 w0.15: v1(46.47,27.96) 45.48,27.96 45.01,28.43 38.62,28.43 37.71,29.35 37.15,29.35 35.26,31.23 30.33,31.23 29.83,31.73 29.51,31.73 28.83,32.41 24.87,32.41 23.78,31.33 19.93,31.33 19.77,31.49 15.8,31.49 15.31,30.99 15.31,29.88 16.3,28.89 16.3,28.89 16.81,28.37 16.81,27.84 v1(17.13,27.52)
  BOTTOM w0.15: v1(46.47,27.96) 46.47,27.99 47.05,28.57 47.05,29 J2.12
DIO29_ANALOG: length 51.1
  TOP w0.15: v1(16.92,26.36) 16.92,26.58 17.71,27.38 20.45,27.38 21.17,26.67 U1.42
  L3 w0.15: v1(44.91,34.13) 44.73,33.95 29.84,33.95 29.09,34.7 23.84,34.7 23.42,35.12 21.31,35.12 19.87,33.68 15.89,33.68 15.58,33.37 14.39,33.37 14.07,33.04 14.07,27.72 15.42,26.37 16.9,26.37 v1(16.92,26.36)
  BOTTOM w0.15: J2.14 45.21,31.57 44.91,31.87 v1(44.91,34.13)
HDC_INT: length 55.6
  TOP w0.15: U1.38 21.49,28.59 17.59,28.59 17.09,29.08 v1(16.77,29.08) ; J2.6 47.08,22.18 45.99,23.27 45.99,24.34 44.93,25.4 R27.1
  L3 w0.15: v1(44.48,27.88) 44.23,28.13 38.5,28.13 37.58,29.05 37.02,29.05 35.14,30.93 30.2,30.93 29.7,31.43 29.38,31.43 28.7,32.11 24.99,32.11 23.91,31.03 19.8,31.03 19.64,31.19 15.93,31.19 15.61,30.86 15.61,30.39 16.77,29.22 v1(16.77,29.08)
  BOTTOM w0.15: v1(44.48,27.88) 45.15,27.22 45.15,26.53 45.64,26.03 45.64,21.71 45.94,21.41 J2.6
LP_RESET: length 7
  TOP w0.15: R7.2 8.7,29.52 8.37,29.18 8.37,28.52 7.42,27.57 4.96,27.57 3.88,26.49
OPT_INT: length 56.7
  TOP w0.15: R32.1 38.82,30.78 v1(38.17,30.78) ; U1.40 21.15,27.67 20.83,27.99 17.34,27.99 17.33,27.99 16.94,27.99 16.93,27.99 16.88,27.99 16.51,27.62 v1(16.51,27.42)
  L3 w0.15: 39.67,33.34 30.14,33.34 30.13,33.34 29.59,33.34 28.84,34.1 23.59,34.1 23.17,34.52 21.56,34.52 20.12,33.08 16.14,33.08 15.83,32.77 14.83,32.77 14.68,32.62 14.68,27.96 15.22,27.42 v1(16.51,27.42) ; 39.67,33.34 44.76,33.34 44.91,33.19 v1(44.91,31.08) ; 39.67,33.34 v1(39.67,32.84)
  BOTTOM w0.15: J2.10 46.04,26.49 45.89,26.64 45.89,28.98 44.91,29.96 v1(44.91,31.08) ; v1(38.17,30.78) 39.52,30.78 39.67,30.93 v1(39.67,32.84)
RX_TX: length 3.1
  TOP w0.25: TR1.5 24.68,21.03 C18.1 ; TR1.5 24.19,21.02 ; TR1.5 24.27,21.12 U1.5
WMCU_MISO: length 65.4
  TOP w0.15: v1(7.62,30.33) 5.11,30.33 3.88,31.57 ; U1.14 28.52,24.21 32.94,24.21 v1(32.98,24.17) ; v1(8.71,18) 8.73,17.98 10.36,17.98 ; v1(34.22,16.72) 37.29,16.72 37.67,16.34 U2.2
  L3 w0.15: v1(8.81,15.71) 8.81,15.27 9.04,15.04 10.87,15.04 12.02,13.89 32.13,13.89 34.22,15.97 v1(34.22,16.72) ; v1(7.62,30.33) 8.04,29.9 8.04,24.51 8.04,23.87 8.05,23.87 8.05,21.46 8.4,21.1 8.4,18.63 8.71,18.32 v1(8.71,18)
  BOTTOM w0.15: v1(34.22,16.72) 34.22,17.29 33.39,18.11 33.39,23.76 v1(32.98,24.17) ; v1(8.71,18) 8.71,15.81 v1(8.81,15.71)
WMCU_MOSI: length 68.6
  TOP w0.15: U2.5 39.39,17.83 v1(39.39,17.43) ; v1(8.07,18.28) 8.27,18.48 10.36,18.48 ; 3.88,29.03 4.96,27.94 7.27,27.94 7.42,28.09 v1(7.42,28.26) ; U1.15 33.32,24.67 33.34,24.68 v1(33.34,24.68)
  L3 w0.15: v1(39.39,17.43) 38.46,16.5 34.71,16.5 ; v1(8.07,18.28) 8.07,21.01 7.73,21.35 7.73,27.96 7.43,28.26 v1(7.42,28.26) ; v1(8.13,15.85) 8.13,15.49 8.89,14.74 10.75,14.74 11.9,13.59 32.26,13.59 34.52,15.85 34.52,16.3 34.71,16.5 ; 34.71,16.5 34.71,17.49 v1(34.2,18)
  BOTTOM w0.15: v1(34.2,18) 33.69,18.51 33.69,24.13 33.34,24.48 v1(33.34,24.68) ; v1(8.13,15.85) 8.07,15.91 v1(8.07,18.28)
WMCU_REED: length 48.2
  TOP w0.15: v1(18.96,29.4) 19.11,29.56 21.96,29.56 U1.36 ; v1(33.36,27.94) 33.26,28.04 33.19,28.04 32.74,28.48 R28.1 32.72,28.64 32.59,28.64 30.06,31.17 v1(30.06,32.51)
  L3 w0.15: v1(22.97,33.55) 23.8,33.55 24.35,33.01 29.08,33.01 29.58,32.51 v1(30.06,32.51) ; v1(48.38,19.58) 47.69,20.27 45.6,20.27 45.3,20.57 45.3,25.76 45.03,26.03 38.32,26.03 36.29,28.06 36.29,28.4 36.1,28.59 34.19,28.59 33.54,27.94 v1(33.36,27.94)
  BOTTOM w0.15: J2.3 49.1,18.87 v1(48.38,19.58) ; v1(18.96,29.4) 18.96,29.77 19.72,30.54 19.72,32.86 20.42,33.55 22.97,33.55 v1(22.97,33.55)
WMCU_RESET: length 99.8
  TOP w0.15: 18.77,30.6 22.45,30.6 22.77,30.29 U1.35 ; 18.77,30.6 17.66,30.6 17.24,30.18 15.98,30.18 15.75,30.41 10.63,30.41 10.5,30.54 10.11,30.54 ; 18.77,30.6 18.77,31.64 18.62,31.79 17.72,31.79 17.66,31.85 ; 18.77,30.6 18.77,30.36 19.08,30.06 R1.1 ; C10.1 16.65,31.79 17.6,31.79 17.66,31.85 ; P2.10 v1(47.1,8.08) ; 10.11,30.54 10.16,30.49 R7.1 ; 10.11,30.54 R6.1 ; v1(17.64,32.6) 17.64,31.87 17.66,31.85 ; v1(46.35,14.22) 46.17,14.39 44.11,14.39 43.49,15.01 P3.4
  L3 w0.15: v1(18.54,38.77) 18.54,38.74 19.44,37.84 27.87,37.84 28.22,38.18 45.24,38.18 45.38,38.04 50.98,38.04 51.62,37.41 51.62,16.25 49.58,14.22 v1(46.35,14.22)
  BOTTOM w0.15: v1(18.54,38.77) 17.64,37.87 v1(17.64,32.6) ; v1(46.35,14.22) 47.27,13.29 47.27,8.23 47.12,8.08 v1(47.1,8.08)
WMCU_SCL: length 45.1
  TOP w0.15: 44.97,35.2 44.97,35.77 R15.1 ; 44.97,35.2 44.18,35.2 43.28,34.3 38.9,34.3 v1(38.69,34.52) ; 44.97,35.2 48.17,35.2 J2.17 ; v1(41.04,32.11) 40.75,31.82 39.88,31.82 39.88,30.77 U6.4 ; U3.6 39.01,21.8 38.77,21.8 38.56,21.59 38.55,21.59 v1(38.48,21.52) 38.22,21.25 35.35,21.25 35.1,21.5 34.71,21.5 34.34,21.13 30.8,21.13 30.8,21.13 27.79,21.13 27.79,21.13 27.7,21.13 26.27,22.57 U1.9
  BOTTOM w0.15: 40.61,32.11 v1(41.04,32.11) ; 40.61,32.11 40.61,32.67 38.77,34.52 v1(38.69,34.52) ; 40.61,32.11 40.14,31.64 40.14,25.32 38.9,24.08 38.9,22.09 38.55,21.74 38.55,21.59 v1(38.48,21.52)
WMCU_SCLK: length 73.2
  TOP w0.15: v1(43.83,32.7) 48.48,32.7 J2.13 ; U2.6 38.17,18.71 38.48,19.02 39.77,19.02 39.78,19.03 v1(39.84,19.03) 39.85,19.03 v1(43.61,19.03) ; v1(39.78,20.15) 39.43,20.51 34.25,20.51 v1(34.23,20.48) ; U5.4 v1(11.13,20.22) ; U1.16 v1(33.93,25.17)
  L3 w0.15: v1(11.13,20.22) 11.13,17.32 13.04,15.42 15.67,15.42 17.12,16.88 26.69,16.88 26.99,16.58 30.74,16.58 31.69,17.53 31.7,17.53 31.97,17.81 31.97,17.81 34.25,20.09 34.25,20.47 v1(34.23,20.48)
  BOTTOM w0.15: v1(43.83,32.7) 43.83,28.4 43.65,28.21 43.65,28.18 43.61,28.15 v1(43.61,19.03) ; v1(33.93,25.17) 33.98,25.12 33.98,24.26 33.99,24.25 33.99,20.73 v1(34.23,20.48) ; v1(39.78,20.15) 39.78,19.08 v1(39.84,19.03)
WMCU_SDA: length 53.8
  TOP w0.15: v1(45.24,37.51) 45.8,38.07 48.5,38.07 J2.19 ; v1(40.47,20.81) 41.54,20.81 U3.1 ; U6.6 39.24,29.32 v1(39.23,29.31) 39.22,29.31 38.45,28.54 37.55,28.54 v1(37.48,28.48) ; U1.10 26.77,22.58 27.92,21.43 30.67,21.43 30.68,21.43 33.99,21.43 37.48,24.93 v1(39.07,24.93)
  L3 w0.15: v1(45.24,37.51) 43.98,36.26 43.57,36.26 43.56,36.24 38.41,36.24 v1(37.19,35.03) ; v1(40.47,20.81) 38.13,20.81 37.79,21.15 37.79,23.79 38.93,24.93 v1(39.07,24.93)
  BOTTOM w0.15: v1(45.24,37.51) 44.99,37.26 R16.1 ; v1(39.07,24.93) 39.07,25.62 39.76,26.31 39.76,26.48 39.76,26.48 39.76,28.78 v1(39.23,29.31) ; v1(37.19,35.03) 37.19,32.96 37.18,32.95 37.18,32.56 37.19,32.55 37.19,28.77 v1(37.48,28.48)
WMCU_SWO: length 27.4
  TOP w0.15: v1(16.13,30.71) 10.75,30.71 10.36,31.1 v1(8.2,31.1) ; v1(26.96,31.53) 26.96,30.93 26.27,30.24 U1.28
  L3 w0.15: v1(16.13,30.71) 19.69,30.71 19.78,30.62 23.93,30.62 24.92,31.62 26.85,31.62 26.93,31.53 v1(26.96,31.53)
  BOTTOM w0.15: 6.42,26.49 7.68,26.49 8.2,27.01 v1(8.2,31.1)
WMCU_TCK: length 62.6
  TOP w0.15: v1(28.97,31.17) 28.97,31.15 27.77,29.95 U1.25 ; P3.3 42.23,15.7 42.23,15.02 42.96,14.29 42.96,12.87 43.27,12.56 44.05,12.56 44.72,11.89 P2.4
  L3 w0.15: v1(42.51,27.65) 42.45,27.65 42.44,27.66 37.63,27.66 36.91,28.37 36.91,28.73 35.01,30.63 31.02,30.63 31.02,30.63 30.27,30.63 30.27,30.63 30.08,30.63 29.58,31.13 29.01,31.13 v1(28.97,31.17) ; v1(8.88,34.9) 8.88,34.14 9.11,33.91 11.36,33.91 12.15,34.7 15.39,34.7 16.72,36.02 25.07,36.02 25.61,35.48 v1(29.07,35.48)
  BOTTOM w0.15: v1(29.07,35.48) 29.26,35.29 29.26,31.46 v1(28.97,31.17) ; P3.3 42.22,17.36 43.14,18.27 43.14,19.23 43.3,19.4 43.3,26.85 v1(42.51,27.65) ; R3.2 8.65,34.99 8.73,34.9 v1(8.88,34.9)
WMCU_TMS: length 70.2
  TOP w0.15: P2.2 44.89,13.76 45.05,13.92 v1(45.5,13.92) ; U1.24 28.47,30.03 29.1,30.66 v1(29.38,30.66)
  L3 w0.15: v1(29.38,30.66) 29.71,30.33 30.14,30.33 34.78,30.33 36.59,28.53 36.59,28.19 37.61,27.17 v1(44.49,27.17) ; v1(7.69,32.34) 7.83,32.34 8.58,31.59 13.62,31.59 13.77,31.74 13.77,33.17 14.27,33.67 15.45,33.67 15.77,33.98 19.74,33.98 21.19,35.42 23.55,35.42 23.97,35 29.39,35 29.64,34.75 v1(29.74,34.75)
  BOTTOM w0.15: v1(29.74,34.75) 29.57,34.58 29.57,30.85 v1(29.38,30.66) ; v1(44.49,27.17) 44.49,26.77 44.84,26.41 44.84,26.4 45.29,25.96 45.29,21.22 45.62,20.89 45.62,14.03 v1(45.5,13.92) 45.38,13.8 41.75,13.8 40.95,14.6 P3.2 ; v1(7.69,32.34) 7.79,32.44 R2.2
N1017630: length 4.2
  TOP w0.15: R24.2 37.04,18.68 U2.8 37.14,18.51 35.85,18.51 35.27,19.09 34.7,19.09 34.7,19.09 C20.1
N1176544: length 2.4
  BOTTOM w0.15: R2.1 8.29,31.88 7.99,31.57 7.43,31.57 7.42,31.57 6.42,31.57
N1176548: length 1.9
  BOTTOM w0.15: R3.1 7.74,34.43 7.42,34.11 6.42,34.11
N1176568: length 2.1
  BOTTOM w0.15: 6.42,36.65 8.04,36.65 R4.1
N1177007: length 2.5
  BOTTOM w0.15: 6.42,39.19 8.2,39.19 8.35,39.34 R5.1
N1409884: length 1.1
  TOP w0.15: U2.3 38.17,16.07 38.05,15.95 38.05,15.34 R23.1
N1409917: length 1.1
  TOP w0.15: U2.7 37.67,18.91 38.02,19.26 R22.1
N2699398: length 9.8
  TOP w0.15: 38.66,22.77 38.68,22.8 U3.5 ; 38.66,22.77 v1(38.27,22.39) ; 38.66,22.77 38.59,22.77 38.25,23.12 38.25,23.12 C21.1 ; U3.3 42.53,24.41 v1(42.71,24.58) 43.28,24.58 R25.1
  L3 w0.15: v1(42.71,24.58) 42.56,24.44 38.9,24.44 38.27,23.8 v1(38.27,22.39)
N2700735: length 2.4
  TOP w0.15: C22.1 31.64,32.36 R26.1 31.64,31.61 31.95,31.3 32.14,31.3 32.16,31.32 U4.1
N2701534: length 3.1
  TOP w0.15: U6.2 41.95,29.96 42.51,30.53 v1(42.51,30.94)
  BOTTOM w0.15: R37.1 42.8,31.68 R36.1 42.81,31.09 42.66,30.94 v1(42.51,30.94)
N2701865: length 5.5
  TOP w0.15: v1(43.36,30.34) 43.64,30.34 43.79,30.19 R29.1 43.77,29.31 43.77,29.31 C25.1 42.51,29.31 42.5,29.32 U6.1
  BOTTOM w0.15: v1(43.36,30.34) 43.36,31.92 43.05,32.23 R36.2
N2717734: length 1.8
  TOP w0.15: R31.2 12,15.41 11.67,15.41 11.56,15.52 11.56,16.6 11.63,16.68
N2718017: length 1.3
  TOP w0.15: R32.2 39.24,30.21 39.48,29.96 U6.5
N2720505: length 1.9
  TOP w0.15: R27.2 40.47,25.37 39.63,24.54 U3.4
N2766833: length 3.2
  BOTTOM w0.15: R11.1 R12.2 11.57,29.87 11.59,29.86 11.59,28.78 11.9,28.47 Q1.1
N2766949: length 8.7
  TOP w0.15: v1(16.26,24.57) R10.1
  BOTTOM w0.15: Q2.3 12.96,22.53 15.85,22.53 16.09,22.77 16.09,24.42 16.24,24.57 v1(16.26,24.57)
N2766991: length 8.5
  BOTTOM w0.15: R13.1 9.13,15 9.31,15.18 9.31,19.51 10.43,20.63 10.43,21.07 10.44,21.07 10.44,21.47 10.43,21.48 R14.2 10.43,21.62 10.43,21.62 10.43,22.26 10.28,22.41 Q2.1
N2767546: length 8.2
  TOP w0.15: v1(12.6,22.14) 14.56,24.1 R9.1
  BOTTOM w0.15: Q3.3 10.23,18.46 10.23,20.01 12.37,22.14 v1(12.6,22.14)
N2767588: length 2.2
  BOTTOM w0.15: R19.1 13.57,19.91 13.57,19.91 R20.2 13.5,19.87 13.18,19.87 12.7,19.39 Q3.1
N2769696: length 2.4
  TOP w0.15: v1(10.77,28.14) 10.29,28.14 9.95,27.8 R8.1
  BOTTOM w0.15: Q1.3 10.16,27.52 v1(10.77,28.14)
N2792373: length 2.3
  TOP w0.15: SW1.2 49.27,8.82 v1(49.28,8.81)
  BOTTOM w0.15: v1(49.28,8.81) 49.28,8.57 49.8,8.05 R17.1
N2796131: length 1.4
  TOP w0.15: SW2.2 5.09,13.39 5.09,13.39 R18.1
N2848828: length 1.1
  TOP w0.15: U7.B2 31.67,39.8 32.1,40.23
N2848936: length 2.9
  TOP w0.32: R34.1 12.84,40.1 12.84,40.1 11.97,40.1 11.59,39.73 P5.3
N3032269: length 10.2
  TOP w0.29: C12.1 16.54,11.3 16.54,11.3 C13.1 16.54,12.06 22.27,17.8 C11.2
N3032277: length 1.7
  TOP w0.29: A1.1 16.53,9.38 16.54,9.38 16.54,9.49 C14.1 16.54,9.97 16.54,9.98 16.54,10.27 C12.2
N3032725: length 1.2
  TOP w0.15: 22.27,21.81 TR1.9
  TOP w0.25: U1.1 22.27,21.81
N3032753: length 1.2
  TOP w0.15: 22.77,21.81 TR1.8
  TOP w0.25: U1.2 22.77,21.81
N3032777: length 1.2
  TOP w0.15: 23.27,21.81 TR1.7
  TOP w0.25: U1.3 23.27,21.81
N3032785: length 8.4
  TOP w0.15: U1.6 24.77,22.51 25.96,21.32 25.96,20.86 26.87,19.95 26.87,18.32 C15.1 29.17,17.57 Y1.1
N3032797: length 1.2
  TOP w0.15: 23.77,21.81 TR1.6
  TOP w0.25: U1.4 23.77,21.81
N3032823: length 5.8
  TOP w0.15: Y1.2 29.17,20.4 C16.1 26.85,20.4 26.26,20.99 26.26,21.5 25.27,22.49 U1.7
N3032853: length 2
  TOP w0.32: C17.1 29.43,29.09 29.01,28.67 U1.23
N3032861: length 4.1
  TOP w0.15: 17.92,23.57 18.28,23.93 20.29,23.93 21.03,24.67 U1.46
N3032929: length 4.6
  TOP w0.15: U1.47 20.95,24.17 19.08,22.29 Y2.1
N3033151: length 20.9
  TOP w0.29: C19.2 23.78,16.82 30.93,9.66 33.56,9.66 34.97,8.25 J1.1
N3041603: length 1.7
  TOP w0.15: 13.61,26.29 12.45,26.29 CR1.2
N3041676: length 1.3
  TOP w0.15: R9.2 13.1,24.67 12.75,25.03 CR1.1
N3041751: length 1.6
  TOP w0.15: CR1.3 10.61,25.75 9.95,26.4 R8.2
N3043961: length 0.9
  TOP w0.15: R28.2 33.3,29.13 U4.2
N3060472: length 1
  TOP w0.25: C11.1 22.27,19.21 TR1.1
N3061599: length 1.4
  TOP w0.32: P1.1 21.1,18.91 21.41,19.21 C9.1
N3065409: length 49.2
  TOP w0.15: v1(13.77,39.01) 14.03,39.27 14.03,39.31 14.31,39.59 R34.2
  L3 w0.15: v1(36.62,35.85) 36.55,35.93 30.74,35.93 30.11,36.56 25.8,36.56 25.44,36.92 15.98,36.92 v1(15.03,35.98)
  BOTTOM w0.15: v1(15.03,35.98) 14.98,35.92 14.37,35.92 ; 14.5,25.36 14.37,25.49 14.37,35.92 ; v1(13.77,39.01) 14.37,38.41 14.37,35.92 ; v1(36.62,35.85) 36.62,33.3 36.88,33.05 36.88,25.88 BT1.1
N3065598: length 66.6
  TOP w0.15: P5.2 10.68,37.79 16.7,37.79 17.02,38.12 33.95,38.12 v1(34.58,37.49)
  BOTTOM w0.15: v1(34.58,37.49) 34.3,37.21 34.3,28.81 35.67,27.45 35.67,21.68 35.92,21.43 37.87,21.43 38.34,20.96 38.34,12.71 48.53,2.51 SW3.3
N3066069: length 27.3
  TOP w0.15: P4.1 41.14,35.83 41.14,35.21 40.64,34.7 39.44,34.7 37.39,36.75 34.65,36.75 33.58,37.82 17.15,37.82 16.49,37.15 R33.2
N3066097: length 5.4
  TOP w0.32: R33.1 14.42,37.15 13,35.73 11.88,35.73 11.88,35.73 P5.1
N3066149: length 48.7
  TOP w0.15: C28.1 29.25,40.11 C26.1 29.37,40.22 30.43,40.22 v1(30.44,40.21) 30.68,39.97 U7.A2
  BOTTOM w0.15: SW3.2 46.61,3.59 37.94,12.26 37.94,20.93 37.75,21.12 35.8,21.12 35.37,21.56 35.37,27.2 34,28.56 34,37.23 31.02,40.22 30.45,40.22 v1(30.44,40.21)
N3085116: length 1
  TOP w0.25: TR1.4 23.77,19.65 23.78,19.65 C19.1
N3297320: length 6.3
  TOP w0.15: 15.16,18.67 15.16,19.04 R30.1 12.89,19.61 12.63,19.36 U5.1 ; 15.16,18.67 C24.1 ; 15.16,18.67 15.16,18.36 14.28,17.47 C23.1 13.86,17.47 13.86,17.48 12.91,17.48
